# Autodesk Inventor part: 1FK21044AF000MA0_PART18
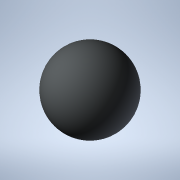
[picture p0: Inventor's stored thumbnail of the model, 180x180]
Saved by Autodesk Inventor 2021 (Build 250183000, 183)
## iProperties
Created: 2025-04
Part Number: 1FK21044AF000MA0_PART18
Material: Generic
Catalog Web Link: www.3dfindit.com
Description: -Servo synchronous motor
Document SubType Name: Modeling
Designer: psAdmin
Mass: 0.137258 g
Surface Area: 1.2868 cm^2
Volume: 0.137258 cm^3
Density: 1 g/cm^3
Appearance: PSOLRGB-212-217-219
Category: PARTsolutions
Title: 1FK21044AF000MA0_PART18
Author: Cadenas PARTsolutions
Comments: Servo synchronous motor
Sending System: PARTsolutions
Preprocessor: ST-DEVELOPER v19.3
PSOL_IDENT_0: {$CADENAS_DATA/23d-libs/siemens_ag/_cat_/39/c4/1fk21044af000ma0.prj},216 {VTYP=3D},{NB=1FK21044AF000
PSOL_IDENT_1: MA0_PART18},{LINA=1FK21044AF000MA0_PART18},{NN=1FK21044AF000MA0_PART18},{NOPRJ=TRUE},{DATE=19.08.202
PSOL_IDENT_2: 5 14:00:33},{GEOMDATE=30.07.2025 02:02:22},{VERSION=},{LINEID=10},{WBVAR=},{WBNUMERIC=}  {NB=1FK2104
PSOL_IDENT_3: 4AF000MA0_PART18},{LINA=1FK21044AF000MA0_PART18},{KT=DUMMY},{PREVIEW=../../../_pool_/cb/72/p_d211_xx
PSOL_IDENT_4: _00434j.png},{DESCSHORT=SIMOTICS S-1FK2 HD, SINAMICS S210 3AC 400V-480V, 1.27 Nm, 3000 rpm},{DESCLON
PSOL_IDENT_5: G=SIMOTICS S-1FK2 HD servo motor M0=1.27 Nm; PN = 0.4 kW at nN=3000 rpm (380-480 V); PN = 0.2 kW at
PSOL_IDENT_6: nN=1500 rpm (200-240 V); degree of protection IP64; cylindrical shaft D19x40mm; absolute encoder 22-
PSOL_IDENT_7: bit + 12-bit multiturn (encoder AM22DQC); with OCC interface; plug size M17, rotatable; SIMOTICS S-1
PSOL_IDENT_8: FK2 servomotorfor a wide range of uses in industrial environments. SIMOTICS S‑1FK2 servomotors are c
PSOL_IDENT_9: ompact synchronous motors with a high dynamic performance that set themselves apart as a result of t
PSOL_IDENT_10: heir high power density, degree of protection and overload capability. The motors are available in t
PSOL_IDENT_11: wo variants: as High Dynamic variant (highest dynamic performance as a result of the low intrinsic m
PSOL_IDENT_12: oment of inertia for applications demanding a high dynamic performance with low moved masses) - and
PSOL_IDENT_13: as Compact variant (precise and stable closed-loop control for medium up to large moved masses as a
PSOL_IDENT_14: result of a medium intrinsic moment of inertia). SIMOTICSS‑1FK2 servomotors fully exploit their stre
PSOL_IDENT_15: ngths in a system with the SINAMICSS210 frequency converter and simple connection using the one cabl
PSOL_IDENT_16: e connection (OCC). Advantages include the short control and positioning times, fast and precise cor
PSOL_IDENT_17: rection of disturbing quantities as well as stable control with a high dynamic performance. The serv
PSOL_IDENT_18: o motors can be configured to address a wide range of requirements. For example with and without hol
PSOL_IDENT_19: ding brake, IP64 or IP65 degree of protection, singleturn or multiturn absolute encoders - to name j
PSOL_IDENT_20: ust a few. Further, the servomotors are available in different shaft heights extending from 20 to 10
PSOL_IDENT_21: 0. A shaft sealing ring is available to achieve an IP65 degree of protection and for subsequent moun
PSOL_IDENT_22: ting at the motor or as spare part. SIMOTICS - the optimum motor for each and every motion control a
PSOL_IDENT_23: pplication.},{INTNO=804766906428},{SUPPLIERALTNO=1FK2104-4AF00-0MA0},{MANUID=1FK21044AF000MA0},{MANU
PSOL_IDENT_24: NAME=Siemens},{MANUTYPEDESC=Synchronous motor 1FK2-HD 1.27 NM},{AAU732=SIMOTICS},{AAO057=S-1FK2},{AA
PSOL_IDENT_25: U734=SIMOTICS S-1FK2 HD servo motor M0=1.27 Nm; PN = 0.4 kW at nN=3000 rpm (380-480 V); PN = 0.2 kW
PSOL_IDENT_26: at nN=1500 rpm (200-240 V); degree of protection IP64; cylindrical shaft D19x40mm; absolute encoder
PSOL_IDENT_27: 22-bit + 12-bit multiturn (encoder AM22DQC); with OCC interface; plug size M17, rotatable;},{AAW338=
PSOL_IDENT_28: Synchronous motor 1FK2-HD 1.27 NM},{AAO742=SIMOTICS},{AAO663=4042948693322},{NOCUPEROU=1},{PRICEQUAN
PSOL_IDENT_29: TITY=1},{QUANTITYMIN=1},{QUANTITYINT=1},{CTN=85015100},{COO=DE},{AAO676=1FK2104-4AF00-0MA0},{AAO677=
PSOL_IDENT_30: Siemens AG},{ORDERUNIT=C62},{CONTENTUNIT=C62}
NB: 1FK21044AF000MA0_PART18
NT: Servo synchronous motor
NBSYN: $MANUID._PART18
LINA: 1FK21044AF000MA0_PART18
CATALOG: SIEMENS
PREVIEW: ../../../_pool_/cb/72/p_d211_xx_00434j.png
DESCSHORT: SIMOTICS S-1FK2 HD, SINAMICS S210 3AC 400V-480V, 1.27 Nm, 3000 rpm
DESCLONG: SIMOTICS S-1FK2 HD servo motor M0=1.27 Nm; PN = 0.4 kW at nN=3000 rpm (380-480 V); PN = 0.2 kW at nN=1500 rpm (200-240 V); degree of protection IP64; cylindrica
INTNO: 804766906428
SUPPLIERALTNO: 1FK2104-4AF00-0MA0
MANUID: 1FK21044AF000MA0
MANUNAME: Siemens
MANUTYPEDESC: Synchronous motor 1FK2-HD 1.27 NM
AAU732: SIMOTICS
AAO057: S-1FK2
AAU734: SIMOTICS S-1FK2 HD servo motor M0=1.27 Nm; PN = 0.4 kW at nN=3000 rpm (380-480 V); PN = 0.2 kW at nN=1500 rpm (200-240 V); degree of protection IP64; cylindrica
AAW338: Synchronous motor 1FK2-HD 1.27 NM
AAO742: SIMOTICS
AAO663: 4042948693322.0
NOCUPEROU: 1
PRICEQUANTITY: 1
QUANTITYMIN: 1
QUANTITYINT: 1
CTN: 85015100
COO: DE
ARTICLENO: 1FK21044AF000MA0_PART18
BOMINFO: 1FK21044AF000MA0_PART18
CREATOR: CADENAS GmbH
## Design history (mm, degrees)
feature "2025_04_17_15_01_28_0038"
body "Solid1"
